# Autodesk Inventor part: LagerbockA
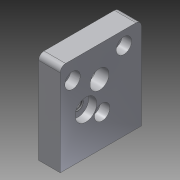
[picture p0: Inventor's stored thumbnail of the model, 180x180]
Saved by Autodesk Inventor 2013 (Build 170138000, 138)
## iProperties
Created: 2012-07
Part Number: LagerbockA
Material: Aluminium 6061
Document SubType Name: Modeling
Designer: rYan
Density: 2.71 g/cm^3
Mass: 19.066 g
Surface Area: 39.1179 cm^2
Volume: 7.03543 cm^3
d1: 34,000 mm
d2: 8,000 mm
d3: 0,00 grd
d15: 7,000 mm
d20: 3,200 mm
d22: 22,000 mm
d24: 35,00 grd
d26: 3,200 mm
d28: 5,700 mm
d29: 3,500 mm
d40: 8,000 mm
d41: 3,000 mm
Author: rYan
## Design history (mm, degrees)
sketch "Skizze1"
  geometry: L1 (-13, 0)-(17, 0); L2 (17, 0)-(17, 34); L3 (17, 34)-(-13, 34); L4 (-13, 34)-(-13, 0); L5 (0, 40.8)-(0, -6.8) reference; L6 (-19, 0)-(23, 0) reference; 1 further point
  constraints: 8 end point, 2 parallel, 1 collinear, 1 horizontal, 1 perpendicular
  dimensions: "d1" = 34 distance of L2.end L1.end; "d69" = 13 distance between parallel lines of L4 L5; "d70" = 17 distance between parallel lines of L2 L5
extrude "Extrusion1" new body sketch "Skizze1" stored distance "d2" = 8; taper "d3" = 0 deg
sketch "Skizze5"
  geometry: L1 (0, 40.8)-(0, -6.8) reference; L2 (17, 34)-(-13, 34) reference; 2 further points
  dimensions: "d59" = 3.5 distance from line of point (-3.5, 15.5) L1; "d72" = 18.5 distance from line of L2 point (-3.5, 15.5)
hole "Radwelle" sketch "Skizze5" at (-3.5, 15.5) diameter "d38" = 4.134; stored, may be unused: countersink angle "d42" = 90 deg, drill point angle "d44" = 0 deg; dims "d39" = 6, "d40" = 8, "d41" = 3, "d43" = 3.2
sketch "Skizze3"
  geometry: L1 (3.5, 15.5)-(1.433, 15.5); L2 (3.5, 15.5)-(-1.519, 22.668); 1 further point
  constraints: 4 end point, 1 horizontal, 1 horizontal alignment, 1 other
  dimensions: "d63" = 55 deg angle of L1 L2; "d64" = 8.75 distance of L1.start L2.end
hole "Motorwelle" sketch "Skizze3" at (-1.519, 22.668) diameter "d15" = 7; stored, may be unused: countersink angle "d19" = 90 deg, drill point angle "d21" = 0 deg; dims "d16" = 6, "d17" = 12.1, "d18" = 3.3, "d20" = 3.2
sketch "Skizze4"
  geometry: L1 (1.519, 22.668)-(12.519, 22.668); L2 (1.519, 22.668)-(10.529, 28.977); C1 r 3.5 at (1.519, 22.668) reference; A1 r 11 centre (1.519, 22.668) between (12.519, 22.668) and (10.529, 28.977); 2 further points
  constraints: 4 end point, 2 coincident, 2 point on circle, 1 centre point, 1 horizontal
  dimensions: "d22" = 22 diameter of A1; "d24" = 35 deg angle of L2 L1
hole "Motorschrauben" sketch "Skizze4" at (10.529, 28.977) diameter "d26" = 3.2; stored, may be unused: countersink angle "d30" = 90 deg, drill point angle "d32" = 0 deg; dims "d27" = 6, "d28" = 5.7, "d29" = 3.5, "d31" = 3.2
pattern_circular "Runde Anordnung2" dims angle "d66" = 360 deg
sketch "Skizze6"
  geometry: L1 (8, 0)-(0, 0) reference; L2 (0, -30)-(8, -30) reference; L3 (4, 0)-(4, -30); 4 further points
  constraints: 2 end point, 2 midpoint, 2 point on line, 1 coincident
  dimensions: "d47" = 10 distance of point (4, -17) point (4, -27); "d48" = 10 distance of point (4, -17) point (4, -7) (= d47)
hole "Montagebohrungen" sketch "Skizze6" at (4, -27), (4, -7), (4, -17) diameter "d51" = 3.242; stored, may be unused: countersink angle "d55" = 90 deg, drill point angle "d57" = 118 deg; dims "d52" = 5, "d53" = 4, "d54" = 2, "d56" = 8
fillet "Rundung1" dims "d71" = 2
node "Volumenkörper1"
